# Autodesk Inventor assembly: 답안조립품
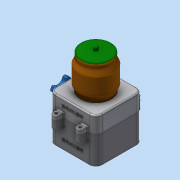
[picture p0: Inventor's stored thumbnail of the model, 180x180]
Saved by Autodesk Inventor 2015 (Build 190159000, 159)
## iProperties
Created: 2018-01
Part Number: 답안조립품
Document SubType Name: Assembly
Designer: SCD-A011
Author: SCD-A011
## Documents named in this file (9)
- C:\Users\SCD-A011\Desktop\480108V1010\답안조립품.iam
- C:\Users\SCD-A011\Desktop\480108V1010\본체.ipt
- C:\Users\SCD-A011\Desktop\480108V1010\본체커버.ipt
- C:\Users\SCD-A011\Desktop\480108V1010\볼트 M3x12.ipt
- C:\Users\SCD-A011\Desktop\480108V1010\볼트 M4x12.ipt
- C:\Users\SCD-A011\Desktop\480108V1010\용기.ipt
- C:\Users\SCD-A011\Desktop\480108V1010\용기캡.ipt
- C:\Users\SCD-A011\Desktop\480108V1010\핸들.ipt
- C:\Users\SCD-A011\Desktop\480108V1010\핸들축.ipt
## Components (2 placed, 2 different names)
1. 핸들:1 — 각도:1
2. 핸들축:1 — 각도:1
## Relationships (1: Angle 1)
- 각도:1 [Angle]: 핸들:1 ↔ 핸들축:1
